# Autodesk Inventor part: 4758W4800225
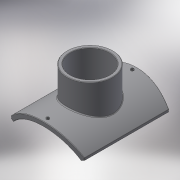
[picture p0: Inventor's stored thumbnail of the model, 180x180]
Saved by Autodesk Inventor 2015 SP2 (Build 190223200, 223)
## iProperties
Created: 2017-10
Part Number: 4758W4800225
Material: Generic
Description: PLASSON LIGHTFIT SADDLE 630-800x225 SPIGOT INLET
Document SubType Name: Modeling
Designer: KIM
Density: 1 g/cm^3
Appearance: Default
Author: KIM
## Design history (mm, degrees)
derived "4758W.ipt"
feature "Solid1::4758W.ipt"
tag "TaggingFeature1"
body "Solid1"
other parameters: "d1" = 22, "d2" = 407, "d3" = 487, "d4" = 0, "d12" = 425.6, "d13" = 14, "d14" = 219.15, "d16" = 5 deg, "d18" = 4, "d19" = 14, "d20" = 0, "d21" = 3, "d22" = 0, "d23" = 552, "d24" = 225, "d26" = 191.25, "d28" = 0, "d34" = 8, "d39" = 4, "d44" = 6.4, "d52" = 0, "d53" = 219.15, "d55" = 0, "d56" = 4, "d_1" = 225, "B_" = 407, "L_" = 487, "x_" = 22, "D_" = 16
